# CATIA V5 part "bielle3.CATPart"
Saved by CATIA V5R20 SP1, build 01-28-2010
Part number: bielle3
Bounding box of the stored display mesh (mm): x -18 to 1, y 160.875 to 265, z -14.963 to 45
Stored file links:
  C:\Users\Fabien-port\Desktop\test\bielle3.CATPart
  C:\Users\Fabien-port\Desktop\test\mecanisme_a_coulisseau.CATProduct
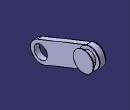
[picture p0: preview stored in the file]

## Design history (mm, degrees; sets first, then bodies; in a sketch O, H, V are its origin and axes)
External parameters (linked from other documents)
  External.largeur_bielle = 15 mm
  External.epaisseur_bielle = 8 mm
  External.rayon_cylindre_bielle = 10 mm
  External.cote_coulisseau = 30 mm
Set1
  Plane1 "Plan_decalage_epaisseur": linked copy from another document
  Point1 "Point_projete": linked copy from another document
  Point2 "PointE": linked copy from another document
Body1 (main body)
  Sketch1 on Plane1, origin (-9, 0, 0), H (0, 1, 0), V (0, 0, 1)
    construction line L1 (175.838, 0) -> (250, 30)
    point P1 (175.838, 0)
    point P2 (250, 30)
    line L2 (170.213, 13.9054) -> (244.375, 43.9054)
    line L3 (255.625, 16.0946) -> (181.463, -13.9054)
    arc A1 centre (250, 30) radius 15 from (244.375, 43.9054) to (255.625, 16.0946) cw
    arc A2 centre (175.838, 0) radius 15 from (181.463, -13.9054) to (170.213, 13.9054) cw
    reference projected point E1 (175.838, 0) from Point1
    reference projected point E2 (250, 30) from Point2
    distance P1 E1 = 0
    distance P2 E2 = 0
    distance L1 L2 = 15 {= External.largeur_bielle}
    tangency: A1 L2, A2 L2, A1 L3, A2 L3
  Pad1: profile Sketch1, direction (-1, 0, 0), length 8 {= External.epaisseur_bielle}
  Sketch2 on Plane1, origin (-9, 221.2702, 0), H (0, 1, 0), V (0, 0, 1)
    point P1 (-45.4322, 0)
    reference projected point E1 (-45.4322, 0) from Point1
    coincidence: E1 P1
  Hole1: placed by Sketch2, at (-9, 175.838, 0) direction (-1, 0, 0), diameter 20 {= External.rayon_cylindre_bielle *2}, depth 8 {= External.epaisseur_bielle}
  Sketch3 on start face of Pad1, origin (-9, 0, 0), H (0, 1, 0), V (0, 0, 1)
    circle A1 centre (250, 30) radius 15
    point P1 (250, 30)
    reference projected point E1 (250, 30) from Point2
    distance P1 E1 = 0
    radius A1 = 15 {= External.cote_coulisseau /2}
  Pad2: profile Sketch3, direction (1, 0, 0), length 1
  Sketch4 on end face of Pad1, origin (-17, 0, 0), H (0, -1, 0), V (0, 0, 1)
    circle A1 centre (-250, 30) radius 15
    point P1 (-250, 30)
    reference projected point E1 (-250, 30) from Point2
    distance P1 E1 = 0
    radius A1 = 15 {= External.cote_coulisseau /2}
  Pad3: profile Sketch4, direction (-1, 0, 0), length 1
  Sketch5 on end face of Pad2, origin (-8, 0, 0), H (0, 1, 0), V (0, 0, 1)
    circle A1 centre (250, 30) radius 10
    point P1 (250, 30)
    reference projected point E1 (250, 30) from Point2
    distance P1 E1 = 0
    radius A1 = 10 {= External.rayon_cylindre_bielle}
  Pad4: profile Sketch5, direction (1, 0, 0), length 8 {= External.epaisseur_bielle}
  Sketch6 on end face of Pad4, origin (0, 0, 0), H (0, 1, 0), V (0, 0, 1)
    circle A1 centre (250, 30) radius 15
    point P1 (250, 30)
    reference projected point E1 (250, 30) from Point2
    radius A1 = 15 {= External.cote_coulisseau /2}
    distance P1 E1 = 0
  Pad5: profile Sketch6, direction (1, 0, 0), length 1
